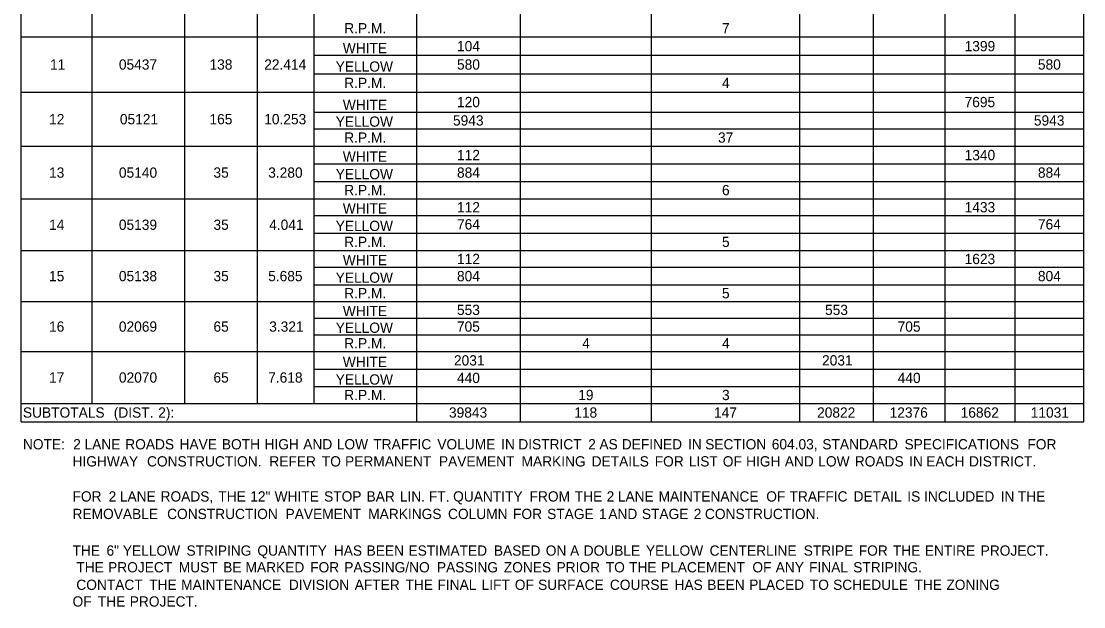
# Model space of a CAD drawing. Extents: x 544250 to 1930787, y -1948365 to 596640.
# Drawn here: x 550069 to 550690, y -1948237 to -1947895 of the extents above; entities that cross this region are included whole.
import ezdxf

# ---------------------------------------------------------------- set-up
doc = ezdxf.new("R2010")
doc.units = 0
doc.layers.add('Default', color=7, linetype='Continuous')

msp = doc.modelspace()

# ---------------------------------------------------------------- linework, layer by layer
at = {"layer": 'Default'}
for p, q in [((550068.96, -1948128.88), (550068.96, -1947540.47)), ((550110.4, -1948118.16), (550110.4, -1947540.47)), ((550164.51, -1948118.16), (550164.51, -1947540.47)), ((550206.93, -1948118.16), (550206.93, -1947540.47)), ((550240.08, -1948118.16), (550240.08, -1947540.47)), ((550300.04, -1948128.88), (550300.04, -1947540.47)), ((550360.49, -1948128.88), (550360.49, -1947540.47)), ((550523.8, -1948128.88), (550523.8, -1947540.47)), ((550608.63, -1948128.88), (550608.63, -1947540.47)), ((550689.55, -1948128.88), (550689.55, -1947540.47)), ((550164.51, -1948118.16), (550164.51, -1947608.72)), ((550206.93, -1948118.16), (550206.93, -1947608.72)), ((550437.03, -1948128.88), (550437.03, -1947608.72)), ((550566.7, -1948128.88), (550566.7, -1947608.72)), ((550649.58, -1948128.88), (550649.58, -1947608.72)), ((550608.63, -1947914.87), (550608.63, -1947893.91)), ((550068.96, -1947904.15), (550300.04, -1947904.15)), ((550300.04, -1947904.15), (550689.55, -1947904.15)), ((550300.04, -1947925.6), (550300.04, -1947904.15)), ((550523.8, -1947925.6), (550523.8, -1947904.15)), ((550240.08, -1947914.87), (550689.55, -1947914.87)), ((550649.58, -1947925.6), (550649.58, -1947914.87)), ((550240.08, -1947925.6), (550300.04, -1947925.6)), ((550240.08, -1947925.6), (550689.55, -1947925.6)), ((550608.63, -1947948.02), (550608.63, -1947925.6)), ((550068.96, -1947936.32), (550300.04, -1947936.32)), ((550300.04, -1947936.32), (550689.55, -1947936.32)), ((550300.04, -1947957.77), (550300.04, -1947936.32)), ((550523.8, -1947957.77), (550523.8, -1947936.32)), ((550240.08, -1947948.02), (550689.55, -1947948.02)), ((550649.58, -1947957.77), (550649.58, -1947948.02)), ((550240.08, -1947957.77), (550300.04, -1947957.77)), ((550240.08, -1947957.77), (550689.55, -1947957.77)), ((550608.63, -1947978.25), (550608.63, -1947957.77)), ((550068.96, -1947968.01), (550300.04, -1947968.01)), ((550300.04, -1947968.01), (550689.55, -1947968.01)), ((550300.04, -1947988.48), (550300.04, -1947968.01)), ((550523.8, -1947988.48), (550523.8, -1947968.01)), ((550240.08, -1947978.25), (550689.55, -1947978.25)), ((550649.58, -1947988.48), (550649.58, -1947978.25)), ((550240.08, -1947988.48), (550300.04, -1947988.48)), ((550240.08, -1947988.48), (550689.55, -1947988.48)), ((550608.63, -1948008.47), (550608.63, -1947988.48)), ((550068.96, -1947998.72), (550300.04, -1947998.72)), ((550300.04, -1947998.72), (550689.55, -1947998.72)), ((550300.04, -1948018.71), (550300.04, -1947998.72)), ((550523.8, -1948018.71), (550523.8, -1947998.72)), ((550240.08, -1948008.47), (550689.55, -1948008.47)), ((550649.58, -1948018.71), (550649.58, -1948008.47)), ((550240.08, -1948018.71), (550300.04, -1948018.71)), ((550240.08, -1948018.71), (550689.55, -1948018.71)), ((550608.63, -1948038.7), (550608.63, -1948018.71)), ((550068.96, -1948028.95), (550300.04, -1948028.95)), ((550300.04, -1948028.95), (550689.55, -1948028.95)), ((550300.04, -1948048.93), (550300.04, -1948028.95)), ((550523.8, -1948048.93), (550523.8, -1948028.95)), ((550240.08, -1948038.7), (550689.55, -1948038.7)), ((550649.58, -1948048.93), (550649.58, -1948038.7)), ((550240.08, -1948048.93), (550300.04, -1948048.93)), ((550240.08, -1948048.93), (550689.55, -1948048.93)), ((550608.63, -1948068.43), (550608.63, -1948048.93)), ((550068.96, -1948058.68), (550300.04, -1948058.68)), ((550240.08, -1948058.68), (550689.55, -1948058.68)), ((550240.08, -1948118.16), (550240.08, -1948058.68)), ((550300.04, -1948078.18), (550300.04, -1948058.68)), ((550523.8, -1948078.18), (550523.8, -1948058.68)), ((550240.08, -1948068.43), (550689.55, -1948068.43)), ((550649.58, -1948078.18), (550649.58, -1948068.43)), ((550240.08, -1948078.18), (550689.55, -1948078.18)), ((550608.63, -1948098.17), (550608.63, -1948078.18)), ((550068.96, -1948087.93), (550300.04, -1948087.93)), ((550240.08, -1948087.93), (550689.55, -1948087.93)), ((550300.04, -1948108.41), (550300.04, -1948087.93)), ((550523.8, -1948108.41), (550523.8, -1948087.93)), ((550240.08, -1948098.17), (550689.55, -1948098.17)), ((550649.58, -1948108.41), (550649.58, -1948098.17)), ((550240.08, -1948108.41), (550689.55, -1948108.41)), ((550608.63, -1948128.88), (550608.63, -1948108.41)), ((550068.96, -1948118.16), (550164.51, -1948118.16)), ((550068.96, -1948118.16), (550110.4, -1948118.16)), ((550110.4, -1948118.16), (550689.55, -1948118.16)), ((550206.93, -1948118.16), (550300.04, -1948118.16)), ((550300.04, -1948118.16), (550689.55, -1948118.16)), ((550300.04, -1948128.88), (550300.04, -1948118.16)), ((550360.49, -1948128.88), (550360.49, -1948118.16)), ((550437.03, -1948128.88), (550437.03, -1948118.16)), ((550523.8, -1948128.88), (550523.8, -1948118.16)), ((550566.7, -1948128.88), (550566.7, -1948118.16)), ((550649.58, -1948128.88), (550649.58, -1948118.16)), ((550068.96, -1948128.88), (550689.55, -1948128.88))]:
    msp.add_line(p, q, dxfattribs=at)

# ---------------------------------------------------------------- texts
for s, p in [('R.P.M.', (550257.62, -1947902.03)), ('7', (550478.27, -1947902.03)), ('WHITE', (550256.78, -1947913.67)), ('104', (550323.48, -1947912.51)), ('1399', (550619.97, -1947912.51)), ('11', (550085.79, -1947923.23)), ('05437', (550126, -1947923.23)), ('138', (550178.92, -1947923.23)), ('22.414', (550210.89, -1947923.23)), ('YELLOW', (550252.64, -1947924.4)), ('580', (550323.48, -1947923.23)), ('580', (550662.78, -1947923.23)), ('R.P.M.', (550257.62, -1947933.96)), ('4', (550478.29, -1947933.96)), ('WHITE', (550256.78, -1947946.82)), ('120', (550323.48, -1947945.17)), ('7695', (550619.95, -1947945.17)), ('12', (550085.24, -1947955.17)), ('05121', (550126.58, -1947955.17)), ('165', (550178.9, -1947955.17)), ('10.253', (550210.88, -1947955.17)), ('YELLOW', (550252.64, -1947956.57)), ('5943', (550321.13, -1947955.9)), ('5943', (550660.43, -1947955.9)), ('R.P.M.', (550257.62, -1947965.89)), ('37', (550475.94, -1947965.89)), ('WHITE', (550256.78, -1947977.05)), ('112', (550323.5, -1947976.13)), ('1340', (550619.98, -1947976.13)), ('13', (550085.21, -1947986.37)), ('05140', (550126.01, -1947986.37)), ('35', (550181.23, -1947986.37)), ('3.280', (550213.22, -1947986.37)), ('884', (550323.48, -1947986.37)), ('884', (550662.78, -1947986.37)), ('YELLOW', (550252.64, -1947987.28)), ('R.P.M.', (550257.62, -1947996.6)), ('6', (550478.27, -1947996.6)), ('WHITE', (550256.78, -1948007.27)), ('112', (550323.5, -1948006.6)), ('1433', (550619.97, -1948006.6)), ('14', (550085.23, -1948016.83)), ('05139', (550125.99, -1948016.83)), ('35', (550181.23, -1948016.83)), ('4.041', (550213.79, -1948016.83)), ('YELLOW', (550252.64, -1948017.51)), ('764', (550323.48, -1948016.59)), ('764', (550662.78, -1948016.59)), ('R.P.M.', (550257.62, -1948026.83)), ('5', (550478.25, -1948026.83)), ('WHITE', (550256.78, -1948037.5)), ('112', (550323.5, -1948036.82)), ('1623', (550619.97, -1948036.82)), ('15', (550085.19, -1948046.82)), ('05138', (550125.99, -1948046.82)), ('35', (550181.23, -1948046.82)), ('5.685', (550213.18, -1948046.82)), ('YELLOW', (550252.64, -1948047.73)), ('804', (550323.48, -1948046.82)), ('804', (550662.78, -1948046.82)), ('R.P.M.', (550257.62, -1948056.81)), ('5', (550478.25, -1948056.81)), ('WHITE', (550256.78, -1948067.23)), ('553', (550323.46, -1948066.56)), ('553', (550538.45, -1948066.56)), ('16', (550085.21, -1948076.31)), ('02069', (550125.99, -1948076.31)), ('65', (550181.23, -1948076.31)), ('3.321', (550213.79, -1948076.31)), ('YELLOW', (550252.64, -1948076.98)), ('705', (550323.44, -1948076.31)), ('705', (550580.84, -1948076.31)), ('R.P.M.', (550257.62, -1948086.06)), ('4', (550396.63, -1948086.06)), ('4', (550478.29, -1948086.06)), ('WHITE', (550256.78, -1948096.97)), ('2031', (550321.71, -1948096.05)), ('2031', (550536.7, -1948096.05)), ('17', (550085.21, -1948106.05)), ('02070', (550126.01, -1948106.05)), ('65', (550181.23, -1948106.05)), ('7.618', (550213.2, -1948106.05)), ('YELLOW', (550252.64, -1948107.21)), ('440', (550323.48, -1948106.29)), ('440', (550580.88, -1948106.29)), ('R.P.M.', (550257.62, -1948116.28)), ('19', (550394.28, -1948116.28)), ('3', (550478.27, -1948116.28)), ('SUBTOTALS', (550069.94, -1948126.52)), (' (DIST.', (550120.77, -1948126.52)), (' 2):', (550146.73, -1948126.52)), ('39843', (550318.79, -1948126.52)), ('118', (550391.96, -1948126.52)), ('147', (550473.61, -1948126.52)), ('20822', (550533.81, -1948126.52)), ('12376', (550576.16, -1948126.52)), ('16862', (550617.66, -1948126.52)), ('11031', (550658.59, -1948126.52)), ('NOTE:', (550069.94, -1948145.05)), ('  2', (550094.83, -1948145.05)), (' LANE', (550103.7, -1948145.05)), (' ROADS', (550127.48, -1948145.05)), (' HAVE', (550159.18, -1948145.05)), (' BOTH', (550183.9, -1948145.05)), (' HIGH', (550208.84, -1948145.05)), (' AND', (550231.45, -1948145.05)), (' LOW', (550251.03, -1948145.05)), (' TRAFFIC', (550272.36, -1948145.05)), (' VOLUME', (550309.75, -1948145.05)), (' IN', (550347.03, -1948145.05)), (' DISTRICT', (550357.06, -1948145.05)), (' 2', (550397.87, -1948145.05)), (' AS', (550404.42, -1948145.05)), (' DEFINED', (550417.49, -1948145.05)), (' IN', (550456.17, -1948145.05)), (' SECTION', (550466.2, -1948145.05)), (' 604.03,', (550505.1, -1948145.05)), (' STANDARD', (550534.64, -1948145.05)), (' SPECIFICATIONS', (550582.64, -1948145.05)), (' FOR', (550654.41, -1948145.05)), ('             HIGHWAY', (550069.94, -1948155.04)), (' CONSTRUCTION.', (550140.19, -1948155.04)), (' REFER', (550211.65, -1948155.04)), (' TO', (550242.28, -1948155.04)), (' PERMANENT', (550255.88, -1948155.04)), (' PAVEMENT', (550310.68, -1948155.04)), (' MARKING', (550358.96, -1948155.04)), (' DETAILS', (550399.89, -1948155.04)), (' FOR', (550436.73, -1948155.04)), (' LIST', (550456.64, -1948155.04)), (' OF', (550476.5, -1948155.04)), (' HIGH', (550490.09, -1948155.04)), (' AND', (550512.7, -1948155.04)), (' LOW', (550532.28, -1948155.04)), (' ROADS', (550553.6, -1948155.04)), (' IN', (550585.31, -1948155.04)), (' EACH', (550595.33, -1948155.04)), (' DISTRICT.', (550620.28, -1948155.04)), ('             FOR', (550069.94, -1948175.52)), (' 2', (550117.78, -1948175.52)), (' LANE', (550124.33, -1948175.52)), (' ROADS,', (550148.11, -1948175.52)), (' THE', (550181.84, -1948175.52)), (' 12"', (550200.48, -1948175.52)), (' WHITE', (550214.72, -1948175.52)), (' STOP', (550243.61, -1948175.52)), (' BAR', (550268.4, -1948175.52)), (' LIN.', (550287.85, -1948175.52)), (' FT.', (550304.82, -1948175.52)), (' QUANTITY', (550318.98, -1948175.52)), (' FROM', (550363.64, -1948175.52)), (' THE', (550390.02, -1948175.52)), (' 2', (550408.66, -1948175.52)), (' LANE', (550415.21, -1948175.52)), (' MAINTENANCE', (550438.99, -1948175.52)), (' OF', (550501.89, -1948175.52)), (' TRAFFIC', (550515.48, -1948175.52)), (' DETAIL', (550552.87, -1948175.52)), (' IS', (550584.25, -1948175.52)), (' INCLUDED', (550594.06, -1948175.52)), (' IN', (550638.8, -1948175.52)), (' THE', (550648.82, -1948175.52)), ('             REMOVABLE', (550069.94, -1948185.75)), (' CONSTRUCTION', (550151.94, -1948185.75)), (' PAVEMENT', (550221.11, -1948185.75)), (' MARKINGS', (550269.4, -1948185.75)), (' COLUMN', (550316.01, -1948185.75)), (' FOR', (550353.98, -1948185.75)), (' STAGE', (550373.89, -1948185.75)), (' 1', (550404.19, -1948185.75)), (' AND', (550409.64, -1948185.75)), (' STAGE', (550429.22, -1948185.75)), (' 2', (550459.52, -1948185.75)), (' CONSTRUCTION.', (550466.07, -1948185.75)), ('             THE', (550069.94, -1948207.15)), (' 6"', (550116.52, -1948207.15)), (' YELLOW', (550126.09, -1948207.15)), (' STRIPING', (550163.26, -1948207.15)), (' QUANTITY', (550204.66, -1948207.15)), (' HAS', (550249.31, -1948207.15)), (' BEEN', (550268.44, -1948207.15)), (' ESTIMATED', (550292.92, -1948207.15)), (' BASED', (550342.78, -1948207.15)), (' ON', (550373.09, -1948207.15)), (' A', (550387.3, -1948207.15)), (' DOUBLE', (550395.24, -1948207.15)), (' YELLOW', (550431.59, -1948207.15)), (' CENTERLINE', (550468.77, -1948207.15)), (' STRIPE', (550523.75, -1948207.15)), (' FOR', (550555.92, -1948207.15)), (' THE', (550575.83, -1948207.15)), (' ENTIRE', (550594.48, -1948207.15)), (' PROJECT.', (550627.1, -1948207.15)), ('THE', (550101.14, -1948216.9)), (' PROJECT', (550117.46, -1948216.9)), (' MUST', (550158.75, -1948216.9)), (' BE', (550184.66, -1948216.9)), (' MARKED', (550197.73, -1948216.9)), (' FOR', (550235.48, -1948216.9)), (' PASSING/NO', (550255.39, -1948216.9)), (' PASSING', (550309.52, -1948216.9)), (' ZONES', (550348.6, -1948216.9)), (' PRIOR', (550379.38, -1948216.9)), (' TO', (550408.14, -1948216.9)), (' THE', (550421.74, -1948216.9)), (' PLACEMENT', (550440.39, -1948216.9)), (' OF', (550493.79, -1948216.9)), (' ANY', (550507.38, -1948216.9)), (' FINAL', (550526.88, -1948216.9)), (' STRIPING.', (550552.67, -1948216.9)), ('CONTACT', (550101.14, -1948227.13)), (' THE', (550141.49, -1948227.13)), (' MAINTENANCE', (550160.14, -1948227.13)), (' DIVISION', (550223.05, -1948227.13)), (' AFTER', (550261.49, -1948227.13)), (' THE', (550291.19, -1948227.13)), (' FINAL', (550309.84, -1948227.13)), (' LIFT', (550335.62, -1948227.13)), (' OF', (550355.01, -1948227.13)), (' SURFACE', (550368.6, -1948227.13)), (' COURSE', (550410.55, -1948227.13)), (' HAS', (550448.3, -1948227.13)), (' BEEN', (550467.43, -1948227.13)), (' PLACED', (550491.9, -1948227.13)), (' TO', (550527.33, -1948227.13)), (' SCHEDULE', (550540.93, -1948227.13)), (' THE', (550588.47, -1948227.13)), (' ZONING', (550607.11, -1948227.13)), ('             OF', (550069.94, -1948236.88)), (' THE', (550111.46, -1948236.88)), (' PROJECT.', (550130.11, -1948236.88))]:
    msp.add_text(s, height=6, dxfattribs=at).set_placement(p)

doc.saveas('drawing.dxf')
